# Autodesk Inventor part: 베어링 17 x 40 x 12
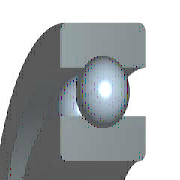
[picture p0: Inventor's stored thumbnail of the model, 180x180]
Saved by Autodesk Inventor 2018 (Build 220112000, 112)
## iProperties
IsCustomPart: 1
Created: 2012-02
Part Number: 베어링 17 x 40 x 12
Material: 강철, 연강
Description: 깊은 그루브 볼 베어링
Document SubType Name: Modeling
Standard: KS B 2023
Designer: mduedu
Standards Organization: KS
Language: ko-KR
Size Designation: 6203 - 17 x 40 x 12
Categories: <MemberInstance><Categories><Category DisplayName="샤프트 부품" InternalName="7f7aeb1f-a693-4053-b835-cee3144e0d98" Mnemonic="SHFT"><Category DisplayName="베어링" Inter
Density: 1 g/cm^3
Appearance: 노란색
Author: mduedu
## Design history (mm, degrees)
sketch "스케치" dims "d0" = 5.98 (= -0.26 x WD + 0.26 x BD)
  geometry: L1 (3.01, 14.25)-(8.99, 14.25); L2 (6, 14.25)-(6, 11.26); L3 (6, 14.25)-(6, 17.24); L4 (3.778, 12.249)-(0, 12.249); L5 (0, 8.5)-(12, 8.5); L6 (3.778, 16.251)-(0, 16.251); L7 (0, 20)-(12, 20); L8 (12, 8.5)-(12, 12.249); L9 (8.222, 12.249)-(12, 12.249); L10 (8.222, 16.251)-(12, 16.251); L11 (12, 20)-(12, 16.251); L12 (-1.4, 0)-(8.4, 0) reference; L13 (0, -0.3)-(0, 5.3) reference
  constraints: 22 end point, 4 point on line, 2 collinear, 2 perpendicular, 2 symmetric about line, 1 midpoint, 1 parallel, 14 other
  dimensions: "d9" = 17 diameter of L5 L12 (= WD); "d11" = 40 diameter of L7 L12 (= BD); "d12" = 12 distance between parallel lines of L8 L13 (= KB); "d13" = 24.498 diameter of L9 L12 (= 0.326 x BD + 0.674 x WD)
revolve "본체" stored, may be unused: angle "d6" = 90 deg
revolve "볼" stored, may be unused: angle "d7" = 90 deg
pattern_circular "IDS_ARRAYBALL[SIMPL:T]" dims angle "d3" = 360 deg
body "Solid1"
fillet "모깎기1" dims "d1" = 0.6 (= KRS)
other parameters: "WD" = 17 [user parameter; used in 5 equation terms], "BD" = 40 [user parameter; used in 5 equation terms], "KB" = 12 [user parameter; used in 1 equation term], "KRS" = 0.6 [user parameter; used in 1 equation term], "d4" = 0, "d5" = 0, "d8" = 0, "d14" = 0, "d15" = 0, "BBA" = 0 [user parameter], "BC0" = 4750000 [user parameter], "BC" = 9560000 [user parameter], "WR" = 8.5 (= 0.5 x WD) [user parameter]
